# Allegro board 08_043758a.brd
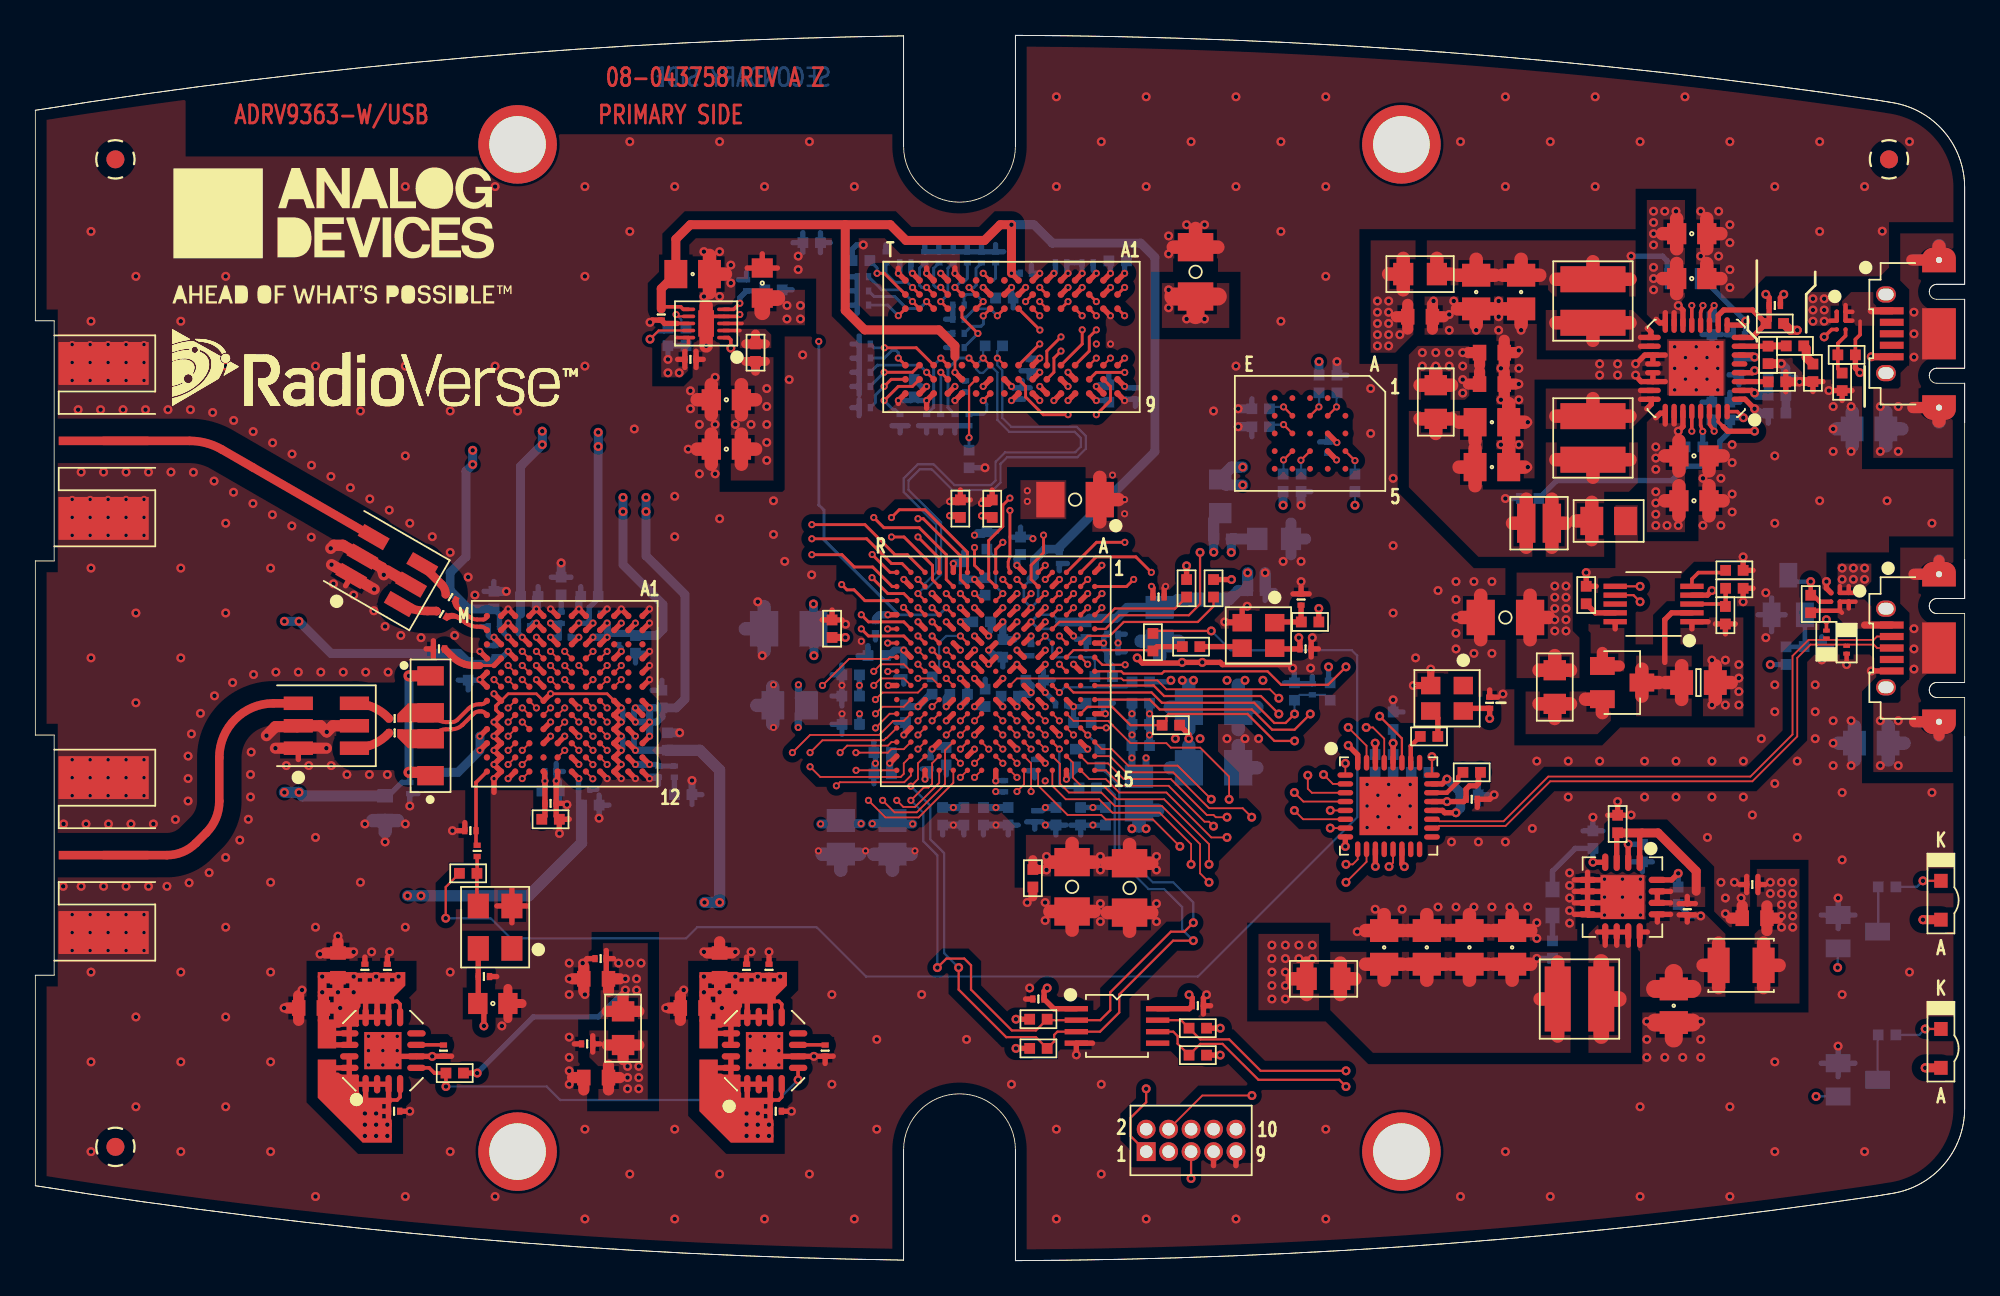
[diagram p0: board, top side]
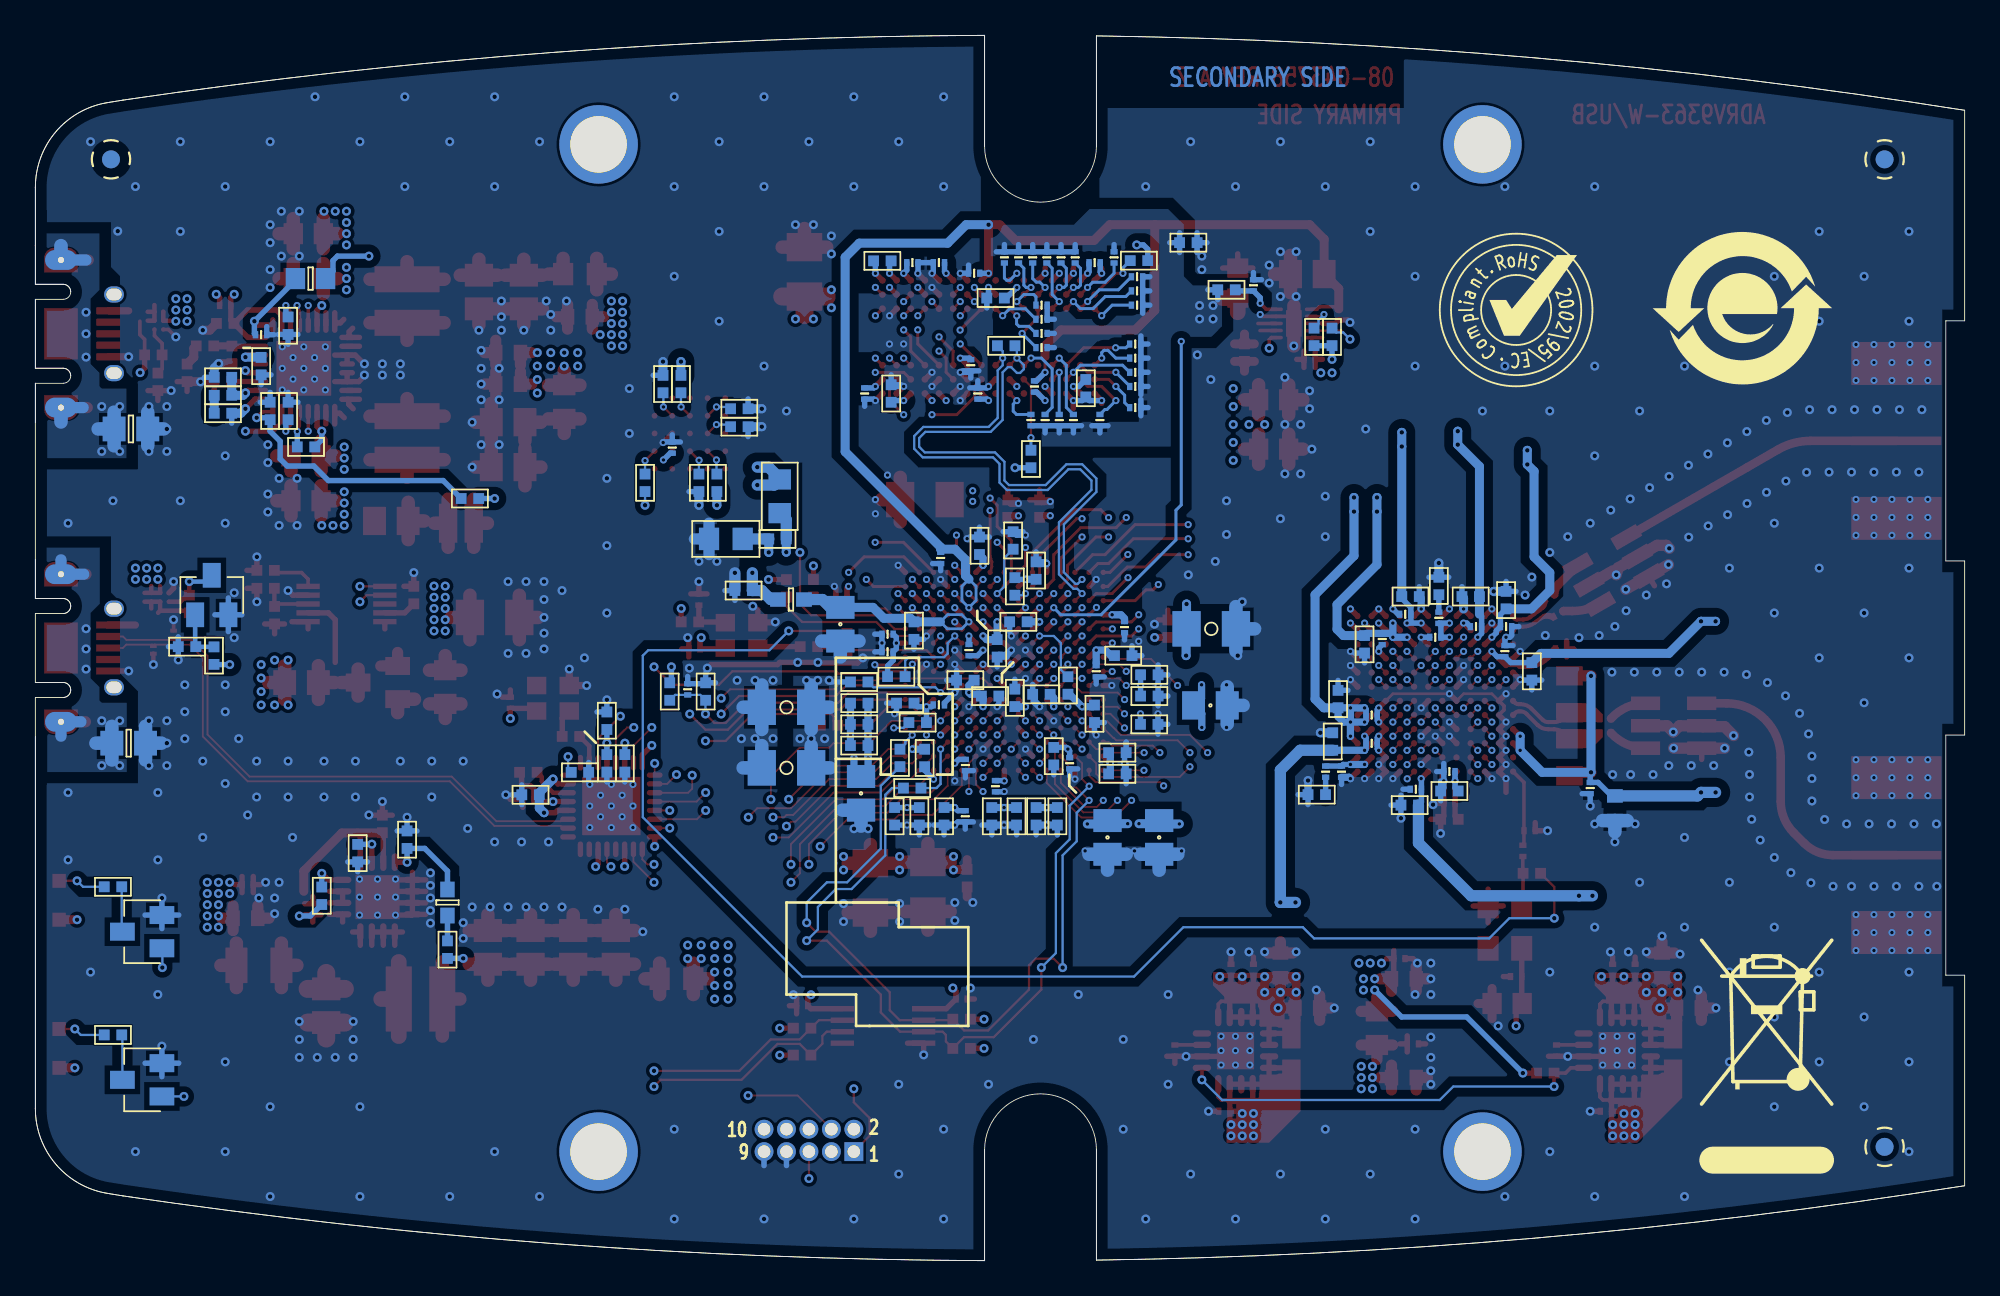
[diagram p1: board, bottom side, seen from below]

Outline 109.14 x 69.34 mm; copper layers: TOP, L2_GND, L3_PWR, L4_GND, L5_SIG, L6_SIG, L7_GND, L8_PWR, L9_GND, BOTTOM. Coordinates in mm from the lower left corner of the outline.
Outline path: 0,65.1 arc(24.48,68.08) 49.11,69.31 ; 0,65.1 arc(24.48,68.08) 49.11,69.31 ; 0,65.1 0,53.18 1.07,53.18 1.07,39.59 0,39.59 0,29.74 1.07,29.74 1.07,16.15 0,16.15 0,4.24 ; 49.11,69.31 49.11,63.06 ; 49.11,69.31 49.11,63.06 ; 0,4.24 arc(24.48,1.26) 49.11,0.03 ; 0,4.24 arc(24.48,1.26) 49.11,0.03 ; 49.11,63.06 arc(52.28,59.9) 55.44,63.06 ; 49.11,6.28 49.11,0.03 ; 49.11,6.28 arc(52.28,9.44) 55.44,6.28 ; 49.11,6.28 49.11,0.03 ; 55.44,6.28 55.44,0 ; 55.44,6.28 55.44,0 ; 55.44,69.34 55.44,63.06 ; 55.44,69.34 arc(79.87,68.37) 104.18,65.67 ; 55.44,69.34 arc(79.87,68.37) 104.18,65.67 ; 55.44,69.34 55.44,63.06 ; 104.18,65.67 105.05,65.53 ; 104.18,65.67 105.05,65.53 ; 55.44,0 arc(79.87,0.97) 104.18,3.67 ; 55.44,0 arc(79.87,0.97) 104.18,3.67 ; 105.05,65.53 arc(107.98,63.88) 109.14,60.73 ; 105.05,65.53 arc(107.98,63.88) 109.14,60.73 ; 104.18,3.67 105.05,3.81 ; 104.18,3.67 105.05,3.81 ; 105.05,3.81 arc(107.98,5.45) 109.14,8.61 ; 105.05,3.81 arc(107.98,5.45) 109.14,8.61 ; 109.14,60.73 109.14,57.47 ; 109.14,60.73 109.14,57.47 ; 107.14,54.82 arc(107.26,55.12) 107.56,55.25 ; 107.14,54.82 arc(107.26,55.12) 107.56,55.25 ; 107.14,54.82 arc(107.26,54.52) 107.56,54.4 109.14,54.4 ; 107.56,55.25 109.14,55.25 ; 107.56,55.25 109.14,55.25 ; 107.14,50.07 arc(107.26,50.37) 107.56,50.5 ; 107.14,50.07 arc(107.26,50.37) 107.56,50.5 ; 107.14,50.07 arc(107.26,49.77) 107.56,49.65 109.14,49.65 ; 107.56,50.5 109.14,50.5 ; 107.56,50.5 109.14,50.5 ; 107.14,37.04 arc(107.26,37.34) 107.56,37.47 ; 107.14,37.04 arc(107.26,37.34) 107.56,37.47 ; 107.14,37.04 arc(107.26,36.74) 107.56,36.62 ; 107.14,37.04 arc(107.26,36.74) 107.56,36.62 ; 107.56,37.47 109.14,37.47 ; 107.56,37.47 109.14,37.47 ; 107.14,32.29 arc(107.26,32.59) 107.56,32.72 ; 107.14,32.29 arc(107.26,32.59) 107.56,32.72 ; 107.14,32.29 arc(107.26,31.99) 107.56,31.87 ; 107.14,32.29 arc(107.26,31.99) 107.56,31.87 ; 107.56,32.72 109.14,32.72 ; 107.56,32.72 109.14,32.72 ; 109.14,55.25 109.14,57.47 ; 109.14,55.25 109.14,57.47 ; 109.14,54.4 109.14,50.5 ; 109.14,54.4 109.14,50.5 ; 109.14,49.65 109.14,47.43 ; 109.14,49.65 109.14,47.43 ; 109.14,37.47 109.14,39.69 ; 109.14,37.47 109.14,39.69 ; 107.56,36.62 109.14,36.62 109.14,32.72 ; 107.56,31.87 109.14,31.87 109.14,29.65 ; 109.14,47.43 109.14,39.69 ; 109.14,29.65 109.14,8.61 ; 109.14,29.65 109.14,8.61

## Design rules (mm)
net group DDR3_CK: nets DDR3_CK_N DDR3_CK_P
net group DDR3_DQS0: nets DDR3_DQS0_N DDR3_DQS0_P
net group DDR3_DQS1: nets DDR3_DQS1_N DDR3_DQS1_P
net group RX1A: nets RX1A_N RX1A_P
net group TX1A: nets TX1A_N TX1A_P
net group UART: nets UART_RX UART_TX
net group USB_OTG: nets USB_OTG_N USB_OTG_P
net group CTRL_IN: nets CTRL_IN0 CTRL_IN1 CTRL_IN2 CTRL_IN3
net group CTRL_OUT: nets IO_L08_34_CTRL_OUT0 IO_L08_34_CTRL_OUT1 IO_L13_34_CTRL_OUT2 IO_L13_34_CTRL_OUT3 IO_L21_34_CTRL_OUT4 IO_L21_34_CTRL_OUT5 IO_L22_34_CTRL_OUT6 IO_L22_34_CTRL_OUT7
net group JTAG: nets JTAG_TCK JTAG_TDI JTAG_TDO JTAG_TMS
net group PWR: nets VCCPLL VDD33_USB VDDA1P1_RX_VCO VTTVREF
net group QSPI: nets PS_MIO01_500_QSPI0_SS_B PS_MIO02_500_QSPI0_IO0 PS_MIO03_500_QSPI0_IO1 PS_MIO04_500_QSPI0_IO2 PS_MIO05_500_QSPI0_IO3 PS_MIO06_500_QSPI0_SCLK
net group RF: nets UNNAMED_7_CAP_I39_N2 UNNAMED_7_CAP_I40_N2 UNNAMED_7_CAP_I51_N1 UNNAMED_7_CAP_I52_N1 UNNAMED_7_CNBNC5P_I55_CNTR UNNAMED_7_CNBNC5P_I56_CNTR
net group RX: nets IO_L01_34_RX_D0 IO_L01_34_RX_D1 IO_L02_34_RX_D2 IO_L02_34_RX_D3 IO_L03_34_RX_D4 IO_L03_34_RX_D5 IO_L04_34_RX_D6 IO_L04_34_RX_D7 IO_L05_34_RX_D8 IO_L05_34_RX_D9 IO_L06_34_RX_D10 IO_L06_34_RX_D11 IO_L07_34_RX_FRAME IO_L12_MRCC_34_DATA_CLK
net group SPI: nets IO_L23_35_SPI_CLK IO_L23_35_SPI_ENB IO_L24_35_SPI_DI IO_L24_35_SPI_DO
net group TX: nets IO_L01_34_FB_CLK IO_L09_34_TX_FRAME IO_L15_34_TX_D0 IO_L15_34_TX_D1 IO_L16_34_TX_D2 IO_L16_34_TX_D3 IO_L17_34_TX_D4 IO_L17_34_TX_D5 IO_L18_34_TX_D6 IO_L18_34_TX_D7 IO_L19_34_TX_D8 IO_L19_34_TX_D9 IO_L20_34_TX_D10 IO_L20_34_TX_D11
net group USB_ULPI: nets PS_MIO28_501_USB0_D4 PS_MIO29_501_USB0_DIR PS_MIO30_501_USB0_STP PS_MIO31_501_USB0_NXT PS_MIO32_501_USB0_D0 PS_MIO33_501_USB0_D1 PS_MIO34_501_USB0_D2 PS_MIO35_501_USB0_D3 PS_MIO36_501_USB0_CLK PS_MIO37_501_USB0_D5 PS_MIO38_501_USB0_D6 PS_MIO39_501_USB0_D7

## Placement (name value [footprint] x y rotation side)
C1  0.1uF  [C0201]  20.29 8.46 0 top
C2  0.01UF  [C0201]  23.09 11.88 270 top
C3  10UF  [C0603#2]  15.59 14.3 180 top
C4  10UF  [C0603#2]  17.12 16.71 90 top
C5  0.1uF  [C0201]  18.64 16.46 90 top
C6  0.1uF  [C0201]  19.91 16.46 90 top
C7  0.047UF  [C0402]  94.84 48.08 270 bottom
C8  0.1uF  [C0201]  97.13 21.28 180 top
C9  10UF  [C0603#2]  97.25 19.38 180 top
C10  0.1uF  [C0201]  41.88 8.46 0 top
C11  47uF  [C0805H60]  92.68 14.42 270 top
C12  0.01UF  [C0201]  44.68 11.88 270 top
C13  0.1uF  [C0201#2]  89.51 24.71 90 top
C14  10UF  [C0603#2]  38.71 16.71 90 top
C15  10UF  [C0603#2]  37.18 14.3 180 top
C16  0.1uF  [C0201]  40.23 16.46 90 top
C17  47uF  [C0805H60]  81.13 17.73 90 top
C18  0.1uF  [C0201]  41.5 16.46 90 top
C19  47uF  [C0805H60]  76.3 17.73 90 top
C20  47uF  [C0805H60]  78.71 17.73 90 top
C21  47uF  [C0805H60]  83.54 17.73 90 top
C22  10UF  [C0603#2]  31.72 10.36 180 top
C23  0.01UF  [C0201]  31.65 36.58 0 bottom
C24  0.01UF  [C0201]  25.94 35.88 180 bottom
C25  0.1uF  [C0201]  31.21 12.27 180 top
C26  0.01UF  [C0201]  31.05 26.68 0 bottom
C27  0.01UF  [C0201]  33.54 30.88 180 bottom
C28  1uF  [C0402]  31.35 37.58 180 bottom
C29  1uF  [C0402]  25.94 37.38 90 bottom
C30  1uF  [C0402]  31.39 25.78 0 bottom
C31  1uF  [C0402]  35.45 31.78 90 bottom
C32  10UF  [C0603#2]  31.72 15.95 180 top
C33  0.1uF  [C0201]  31.98 17.09 180 top
C34  1uF  [C0402]  27.94 37.58 0 bottom
C35  1uF  [C0402]  35.75 29.38 90 bottom
C36  1uF  [C0402]  24.48 33.35 270 bottom
C37  1uF  [C0402]  33.95 34.88 270 bottom
C38  1uF  [C0402]  29.15 26.58 0 bottom
C39  0.01UF  [C0201]  27.64 35.88 0 bottom
C40  0.01UF  [C0201]  33.54 29.28 180 bottom
C41  0.01UF  [C0201]  26.01 34.49 90 bottom
C42  0.01UF  [C0201]  32.95 35.18 270 bottom
C43  0.01UF  [C0201]  29.14 25.88 0 top
C44  0.01UF  [C0201]  29.15 27.68 0 bottom
C45  1uF  [C0402]  29.14 24.98 0 top
C46  0.1uF  [C0201]  71.85 34.62 0 top
C47  0.1uF  [C0201]  72.24 32.33 90 bottom
C48  0.1uF  [C0201]  73.11 46.01 90 bottom
C49  100uF  [C1206H71]  66.65 31.32 0 bottom
C50  4.7uF  [C0402]  62.53 31.55 0 bottom
C51  0.47uF  [C0402]  47.6 34.24 180 bottom
C52  0.1uF  [C0201]  60.93 35.45 0 bottom
C53  0.01UF  [C0201]  60.93 34.45 0 bottom
C54  100uF  [C1206H71]  58.82 43.06 0 top
C55  4.7uF  [C0402]  55.73 40.45 90 bottom
C56  0.47uF  [C0402]  45.07 35.76 90 top
C57  0.47uF  [C0402]  54.13 42.55 90 top
C58  0.47uF  [C0402]  52.33 42.55 90 top
C59  0.47uF  [C0402]  52.53 39.05 90 bottom
C60  0.1uF  [C0201]  63.54 37.56 0 top
C61  0.01UF  [C0201]  47.52 35.85 270 bottom
C62  0.01UF  [C0201]  37.06 51 180 top
C63  0.01UF  [C0201]  56.03 55.88 180 bottom
C64  100uF  [C1206H71]  61.9 21.09 270 top
C65  47uF  [C0805H60]  48.49 23.95 270 bottom
C66  4.7uF  [C0402]  53.73 31.85 90 bottom
C67  4.7uF  [C0402]  52.53 25.14 270 bottom
C68  0.47uF  [C0402]  56.43 21.64 270 top
C69  0.47uF  [C0402]  59.93 31.55 0 bottom
C70  0.47uF  [C0402]  54.73 34.65 270 bottom
C71  100uF  [C1206H71]  58.65 21.16 270 top
C72  0.47uF  [C0402]  52.23 32.05 0 bottom
C73  4.7uF  [C0402]  53.53 36.15 0 bottom
C74  0.47uF  [C0402]  55.13 31.95 180 bottom
C75  0.47uF  [C0402]  56.53 32.85 0 bottom
C76  100uF  [C1206H71]  42.62 35.75 180 bottom
C77  47uF  [C0805H60]  42.67 31.42 180 bottom
C78  4.7uF  [C0402]  46.12 31.95 180 bottom
C79  10UF  [C0603]  41.12 55.32 90 top
C80  0.01UF  [C0201]  40.23 55.19 90 bottom
C81  0.22UF  [C0805]  37.18 55.83 0 top
C82  10UF  [C0603]  39.09 45.92 180 top
C83  10UF  [C0603]  39.09 48.71 180 top
C84  0.01UF  [C0201]  35.41 53.54 270 top
C85  47uF  [C0805H60]  63.6 36.01 270 bottom
C86  4.7uF  [C0402]  49.72 49.37 270 bottom
C87  4.7uF  [C0402]  60.73 49.07 90 bottom
C88  0.47uF  [C0402]  61.23 56.58 180 bottom
C89  0.47uF  [C0402]  54.82 54.47 0 bottom
C90  0.47uF  [C0402]  46.12 33.15 180 bottom
C91  0.1uF  [C0201]  55.82 49.07 90 bottom
C92  0.1uF  [C0201]  56.22 50.67 270 bottom
C93  0.47uF  [C0402]  67.16 40.84 0 bottom
C94  0.1uF  [C0201]  59.52 56.48 180 bottom
C95  0.1uF  [C0201]  58.02 56.48 0 bottom
C96  0.1uF  [C0201]  49.22 56.47 180 bottom
C97  0.1uF  [C0201]  62.23 49.07 270 bottom
C98  0.1uF  [C0201]  56.33 34.55 90 bottom
C99  0.01UF  [C0201]  57.92 39.76 90 bottom
C100  100uF  [C1206H71]  65.63 55.95 90 top
C101  4.7uF  [C0402]  43.91 57.6 180 bottom
C102  0.01UF  [C0201]  52.62 49.47 270 bottom
C103  47uF  [C0805H60]  62.43 26.44 270 bottom
C104  47uF  [C0805H60]  45.57 23.95 270 bottom
C105  4.7uF  [C0402]  55.03 25.14 270 bottom
C106  4.7uF  [C0402]  51.33 25.14 270 bottom
C107  4.7uF  [C0402]  60.53 25.14 270 bottom
C108  4.7uF  [C0402]  46.13 30.35 180 bottom
C109  0.47uF  [C0402]  53.63 25.14 270 bottom
C110  0.47uF  [C0402]  51.53 28.55 270 bottom
C111  0.47uF  [C0402]  58.83 28.44 270 bottom
C112  0.47uF  [C0402]  47.93 28.75 180 bottom
C113  0.47uF  [C0402]  59.13 25.14 270 bottom
C114  0.47uF  [C0402]  47.93 27.55 180 bottom
C115  0.47uF  [C0402]  57.74 25.14 270 bottom
C116  0.47uF  [C0402]  49.22 30.95 270 bottom
C117  0.1uF  [C0201]  56.53 25.14 270 bottom
C118  0.1uF  [C0201]  50.63 28.15 270 bottom
C119  0.01UF  [C0201]  54.83 26.85 270 bottom
C120  0.01UF  [C0201]  49.13 33.35 270 bottom
C121  10UF  [C0603]  25.88 14.55 0 top
C122  0.1uF  [C0201]  25.37 16.08 0 top
C123  18pF  [C0201]  24.99 23.19 90 top
C124  18pF  [C0201]  24.61 24.33 180 top
C125  1000pF  [C0201]  29.94 35.28 180 bottom
C126  1uF  [C0402]  29.74 38.18 270 bottom
C127  1uF  [C0402]  36.65 26.37 0 bottom
C128  1000pF  [C0201]  35.25 27.67 270 bottom
C129  1000pF  [C0201]  21.18 26.74 90 bottom
C130  10UF  [C0603#2]  19.78 25.6 270 bottom
C131  18pF  [C0201]  20.32 29.86 180 top
C132  18pF  [C0201]  20.32 30.67 180 top
C133  18pF  [C0201]  22.98 36.59 330 top
C134  18pF  [C0201]  23.49 37.55 330 top
C135  10UF  [C0603]  93.83 45.54 0 top
C136  10UF  [C0603]  93.7 55.57 0 top
C137  10UF  [C0603]  93.83 43 0 top
C138  10UF  [C0603]  93.7 58.11 0 top
C139  0.047UF  [C0402]  94.84 52.91 90 bottom
C140  1uF  [C0402]  76.81 30.55 90 bottom
C141  1uF  [C0402]  98.4 53.03 0 top
C142  150pF  [C0402]  98.52 49.98 180 bottom
C143  180pF  [C0402]  98.02 51.25 90 top
C144  3300pF  [C0402]  99.54 51.76 0 top
C145  47uF  [C0805H60]  81.51 54.81 270 top
C146  22UF  [C0805H53]  89 41.86 0 top
C147  5600pF  [C0402]  98.52 47.95 0 bottom
C148  47uF  [C0805H60]  84.05 54.81 270 top
C149  47uF  [C0805H60]  82.4 47.44 0 top
C150  47uF  [C0805H60]  82.4 44.9 0 top
C151  10UF  [C0603#2]  78.33 53.41 0 top
C152  10UF  [C0603#2]  82.4 51.38 0 top
C153  10UF  [C0603#2]  82.4 49.6 0 top
C154  1uF  [C0402]  75.79 28.14 270 bottom
C155  0.047UF  [C0402]  87.73 37.67 90 top
C156  0.47uF  [C0402]  96.11 39.06 0 top
C157  100uF  [C1206H71]  83.16 36.4 180 top
C158  100uF  [C1206H71]  66.65 27.89 0 bottom
C159  4.7uF  [C0402]  62.53 30.35 0 bottom
C160  0.47uF  [C0402]  62.53 29.15 0 bottom
C161  0.1uF  [C0201]  56.53 28.05 270 bottom
C162  0.01UF  [C0201]  58.03 31.45 180 bottom
C163  0.1uF  [C0201]  82.27 31.57 270 top
C164  0.1uF  [C0201]  81.25 26.11 0 top
C165  2.2uF  [C0402]  81.13 26.36 0 bottom
C166  0.1uF  [C0201]  56.74 14.81 0 top
C167  0.1uF  [C0201]  65.76 14.42 0 top
C168  1uF  [C0402]  76.81 28.14 270 bottom
C174  4.7uF  [C0402]  69.07 37.92 0 bottom
C178  0.47uF  [C0402]  59.44 35.65 270 bottom
D1  SESD0201X1UN-0020-09  [D0201]  102.46 34.57 270 top
D2  SESD0201X1UN-0020-09  [D0201]  101.32 35.43 90 top
DS1  LTST-S220TBKT  [LED0804]  107.8 20.39 270 top
DS2  LTST-S220TBKT  [LED0804]  107.8 12.01 270 top
E1  100OHM  [L0805]  72.87 15.95 180 top
E2  100OHM  [L0805]  78.33 55.83 180 top
E3  100OHM  [L0805]  79.22 48.59 90 top
E4  100OHM  [L0805]  33.25 13.15 90 top
E5  100OHM  [L0805]  67.03 43.25 270 bottom
E6  100OHM  [L0805]  70.08 40.84 180 bottom
E7  100OHM  [L0805]  85.95 32.46 90 top
L1  0.47uH  [L1210H67]  96.49 16.71 180 top
L2  1.5uH  [LSMSQ157H83]  88.11 54.3 90 top
L3  1.5uH  [LSMSQ157H83]  88.11 46.56 270 top
L4  1uH  [LSMSQ157H83]  87.35 14.81 180 top
L5  180NH  [LSMSQ79H41]  85.06 41.73 180 top
L8  330nH  [L0805-F]  22.36 28.49 90 top
L9  330nH  [L0805-F]  22.36 32.05 270 top
L12  600OHMS  [L0603]  66.39 37.41 180 bottom
NOREF  -  []  108.15 5.67 0 top
NOREF#2  -  [unnamed#2]  4.53 62.32 0 top
NOREF#3  -  []  52.28 63.06 0 top
NOREF#4  -  []  69.79 0.36 0 top
NOREF#5  -  []  202.3 71.42 0 top
NOREF#6  -  []  -88.22 48.51 0 top
NOREF#7  -  []  297.27 339.09 0 top
NOREF#8  -  [unnamed#2]  77.28 63.17 180 top
NOREF#9  -  []  -98.72 -116.59 0 top
NOREF#10  -  []  109.14 36.62 0 top
NOREF#11  -  []  0 4.24 0 top
NOREF#12  -  []  109.14 50.5 0 top
NOREF#13  -  []  109.14 54.4 0 top
NOREF#14  -  []  0 29.74 0 top
NOREF#15  -  []  -98.72 -116.59 0 top
NOREF#16  -  []  27.28 6.17 0 top
NOREF#17  -  [unnamed#2]  104.86 62.32 0 top
NOREF#18  -  []  109.14 8.61 0 top
NOREF#19  -  [unnamed#2]  27.28 63.17 180 top
NOREF#20  -  []  109.46 31.95 0 top
NOREF#21  -  []  0 65.1 0 top
NOREF#22  -  [unnamed#2]  27.28 6.17 180 top
NOREF#23  -  []  51.64 6.28 0 top
NOREF#24  -  []  17.37 57.99 0 top
NOREF#25  -  []  49.11 0.03 0 top
NOREF#26  -  []  1.07 16.15 0 top
NOREF#27  -  []  -98.72 -116.59 0 top
NOREF#28  -  [unnamed#2]  4.53 6.44 0 top
NOREF#29  -  []  0 39.59 0 top
NOREF#30  -  []  -37.76 254.25 0 top
NOREF#31  -  []  55.44 0 0 top
NOREF#32  -  []  52.28 6.28 0 top
NOREF#33  -  []  -98.72 -116.59 0 top
NOREF#34  -  []  49.11 0.03 0 top
NOREF#35  -  []  0 53.18 0 top
NOREF#36  -  []  27.28 6.17 0 top
NOREF#37  -  [unnamed#2]  77.28 6.17 180 top
NOREF#38  -  []  0 4.24 0 top
NOREF#39  -  []  109.14 31.87 0 top
NOREF#40  -  []  109.14 49.65 0 top
NOREF#41  -  []  109.14 37.47 0 top
NOREF#42  -  []  109.14 55.25 0 top
NOREF#43  -  []  0 16.15 0 top
NOREF#44  -  []  49.11 69.31 0 top
NOREF#45  -  []  55.44 0 90 top
NOREF#46  -  []  109.14 32.72 0 top
NOREF#47  -  []  0 65.1 0 top
NOREF#48  -  []  12.57 53.9 180 bottom
NOREF#49  -  [unnamed#2]  104.86 62.32 180 bottom
NOREF#50  -  [unnamed#2]  4.53 6.44 180 bottom
NOREF#51  -  [unnamed#2]  4.53 62.32 180 bottom
NOREF#52  -  []  1.93 21.82 180 bottom
NOREF#53  -  []  25.37 53.79 180 bottom
P1  FTSH-105-01-L-D  [CNHDR2X5H219]  62.84 6.17 0 top
P2  47590-0001  [CNMOLEX47590-0001]  109.14 34.67 180 top
P3  47590-0001  [CNMOLEX47590-0001]  109.14 52.45 180 top
Q1  BSS138LT1G  [SOT23]  103.1 18.62 90 bottom
Q2  BSS138LT1G  [SOT23]  99.16 37.67 180 bottom
Q3  SI2304BDS-T1-E3  [SOT23]  89.76 32.71 270 top
Q4  BSS138LT1G  [SOT23]  103.1 10.23 90 bottom
R1  10  [R0201]  93.44 19.89 270 top
R2  27.4K  [R0402]  88.11 23.82 270 bottom
R3  46.4K  [R0402]  90.9 23.06 90 bottom
R4  17.8K  [R0603#2]  85.82 20.27 270 bottom
R5  10K  [R0402]  23.72 10.61 180 top
R6  10K  [R0402]  92.94 20.65 90 bottom
R7  1K  [R0402]  85.82 17.6 270 bottom
R8  10K  [R0402]  72.11 36.14 180 top
R9  10K  [R0201]  71.6 37.41 90 top
R10  0  [R0402]  63.22 35 270 top
R11  0  [R0402]  74.65 44.02 270 bottom
R12  39  [R0402]  65.38 34.74 180 top
R13  20K  [R0402]  73.25 32.2 270 bottom
R14  240  [R0402]  72.62 49.6 270 bottom
R15  0  [R0402]  71.22 32.2 90 bottom
R16  120  [R0201]  51.92 56.77 90 bottom
R17  120  [R0201]  46.82 54.88 180 bottom
R18  120  [R0201]  46.91 50.27 180 bottom
R19  120  [R0201]  48.92 47.57 270 bottom
R20  120  [R0201]  46.92 48.27 180 bottom
R21  120  [R0201]  52.02 47.57 270 bottom
R22  120  [R0201]  46.92 51.87 180 bottom
R23  120  [R0201]  51.12 56.77 90 bottom
R24  120  [R0201]  50.32 56.77 90 bottom
R25  120  [R0201]  48.12 56.77 90 bottom
R26  120  [R0201]  46.82 55.68 180 bottom
R27  120  [R0201]  46.91 49.47 180 bottom
R28  120  [R0201]  50.42 47.57 270 bottom
R29  120  [R0201]  46.92 51.07 180 bottom
R30  120  [R0201]  51.22 47.57 270 bottom
R31  120  [R0201]  52.22 54.07 180 bottom
R32  120  [R0201]  52.22 52.47 180 bottom
R33  120  [R0201]  54.32 56.77 90 bottom
R34  120  [R0201]  46.82 54.07 180 bottom
R35  120  [R0201]  52.72 56.77 90 bottom
R36  120  [R0201]  52.22 51.67 180 bottom
R37  120  [R0201]  52.22 53.27 180 bottom
R38  120  [R0201]  52.82 47.57 270 bottom
R39  120  [R0201]  53.52 56.77 90 bottom
R40  240  [R0402]  53.83 40.75 90 bottom
R41  240  [R0402]  53.73 38.15 90 bottom
R42  1K  [R0402]  46.71 56.59 180 bottom
R43  0  [R0402]  41.76 54.94 180 bottom
R44  0  [R0402]  40.74 51.38 90 top
R45  0  [R0402]  60.43 33.05 180 bottom
R46  4.7K  [R0402]  50.73 32.55 270 bottom
R47  4.7K  [R0402]  65.12 38.05 90 top
R48  470  [R0402]  104.75 21.16 180 bottom
R49  14.3K  [R0201]  22.83 34.62 0 top
R50  0  [R0402]  24.48 21.92 0 top
R51  1  [R0201]  29.74 36.38 270 bottom
R52  1  [R0201]  36.15 27.67 270 bottom
R53  27.4K  [R0402]  98.52 49.73 180 top
R54  4.7K  [R0402]  96.37 50.62 270 bottom
R55  1K  [R0805]  103.86 29.28 180 bottom
R56  10  [R0201]  98.4 54.05 180 top
R58  1K  [R0805]  103.73 47.06 180 bottom
R59  100K  [R0402]  93.83 46.05 180 bottom
R60  10K  [R0402]  98.52 48.97 0 bottom
R61  10K  [R0402]  100.56 50.24 90 top
R62  17.8K  [R0603]  93.57 55.57 0 bottom
R63  14.3K  [R0201]  96.37 52.4 180 bottom
R64  46.4K  [R0402]  84.55 43.13 180 bottom
R65  23.2K  [R0402]  95.86 48.08 270 bottom
R66  240  [R0402]  99.03 34.24 90 bottom
R67  10K  [R0402]  100.56 34.74 0 bottom
R68  10K  [R0402]  102.46 51.25 180 top
R69  10K  [R0402]  102.21 49.73 270 top
R70  10K  [R0402]  100.43 37.16 90 top
R71  10K  [R0402]  95.6 36.52 90 top
R72  10K  [R0402]  96.11 38.05 0 top
R73  0.05  [R0805]  94.08 32.71 180 top
R74  10K  [R0402]  64.23 30.3 180 top
R75  10K  [R0402]  81.25 27.63 180 top
R76  20K  [R0402]  59.23 30.45 0 bottom
R77  8.06K  [R0402]  78.33 27.63 180 bottom
R78  4.7K  [R0402]  56.74 12.01 0 top
R79  4.7K  [R0402]  56.74 13.66 0 top
R80  4.7K  [R0402]  65.76 11.63 180 top
R81  4.7K  [R0402]  65.76 13.15 180 top
R82  39  [R0402]  78.84 29.66 0 top
R83  20K  [R0402]  62.53 32.75 180 bottom
R84  20K  [R0402]  66.65 38.05 90 top
R85  0  [R0402]  59.54 26.74 0 bottom
R86  0  [R0402]  60.23 28.45 270 bottom
R87  470  [R0402]  104.75 12.77 180 bottom
R116  20K  [R0402]  73.63 49.6 90 bottom
R119  20K  [R0402]  69.31 48.21 180 bottom
R120  20K  [R0402]  69.31 47.19 180 bottom
R121  20K  [R0402]  71.6 44.02 270 bottom
R122  20K  [R0402]  70.58 44.02 270 bottom
R142  80.6  [R0402]  54.22 51.77 180 bottom
R165  240  [R0402]  52.82 45.36 270 bottom
R221  10K  [R0402]  35.79 52.27 90 bottom
R222  10K  [R0402]  36.8 52.27 90 bottom
RX1A  142-0701-871  [CNSMARAL687W375H171]  3.61 46.39 180 top
T1  TCM1-63AX+  [TSML150W160H160]  19.88 39.05 60 top
T5  TCM1-63AX+  [TSML150W160H160]  16.46 30.27 90 top
TX1A  142-0701-871  [CNSMARAL687W375H171]  3.61 22.95 180 top
U1  ADP1754ACPZ-1.3  [QFN16_4X4_PAD2_1X2_1]  19.66 11.88 0 top
U2  MT41K256M16TW-107 IT:P  [FBGA96_C]  55.22 52.27 180 top
U3  ADP2164ACPZ  [QFN16_4X4_PAD2_5X2_5]  89.78 20.57 180 top
U4  XC7Z010-1CLG225C  [CSPBGA225]  54.33 33.35 180 top
U5  AD9363ABCZ  [BGA144-2]  29.94 32.08 180 top
U6  ADP2114ACPZ  [QFN32_5X5_PAD3_1X3_1]  93.95 50.49 90 top
U7  ADP1754ACPZ-1.3  [QFN16_4X4_PAD2_1X2_1]  41.25 11.88 0 top
U8  NCP339AFCT2G  [WLCSP6]  102.15 53.19 270 top
U9  NCP339AFCT2G  [WLCSP6]  102.08 37.54 180 top
U10  ADM1177-1ARMZ  [RM10]  91.54 37.16 90 top
U11  TCA9517DGKR  [MSOP8]  61.19 13.28 270 top
U13  N25Q256A11E1240  [TBGA24]  72.11 46.81 180 top
U14  TPS51206DSQR  [SON10_2X2_PAD1_5X0_9]  37.95 53.03 90 top
U15  USB3320C-EZK  [QFN32_5X5_PAD3_3X3_3]  76.55 25.73 270 top
Y1  24.000MEGHZ  [YSML98W79H35]  79.86 31.82 180 top
Y2  33.333MEGHZ  [YSML98W79H35]  69.19 35.38 180 top
Y3  40MEGHz  [YSML126W98H47]  26.01 18.87 90 top

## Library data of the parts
C1 C5 C6 C8 C10 C16 C18 C25 C33 C46-C48 C52 C60 C91 C92 C94-C98 C117 C118 C122 C161 C163 C164 C166 C167 = CAP: User Part Number: UPN; Tolerance: 20; part number: CAP_SM-0.1UF,16V,20,E017331,C0201; tolerance: 20
C2 C12 C23 C24 C26 C27 C39-C44 C53 C61-C63 C80 C84 C99 C102 C119 C120 C162 = CAP: User Part Number: UPN; Tolerance: 10; part number: CAP_SM-0.01UF,10V,10,E007201,C0201; tolerance: 10
C3 C4 C9 C14 C15 C22 C32 C79 C82 C83 C121 C130 C135-C138 C151-C153 = CAP: Tolerance: 20; User Part Number: UPN; alternate symbols: C0603L_ALT; part number: CAP_SM-10UF,6.3V,20,E007143,C0603; tolerance: 20
C7 C139 C155 = CAP: Tolerance: 10; User Part Number: UPN; alternate symbols: C0402_ALT; part number: CAP_SM-0.047UF,25V,10,E006454,C0402; tolerance: 10
C11 C17 C19-C21 C65 C77 C85 C103 C104 C145 C148-C150 = CAP: Tolerance: 20; User Part Number: UPN; part number: CAP_SM-47UF,6.3V,20,E008247,C0805H60; tolerance: 20
C13 = CAP: Tolerance: 20; User Part Number: UPN; alternate symbols: C0402_ALT; part number: CAP_SM-0.1UF,16V,20,E017331,C0201; tolerance: 20
C28-C31 C34-C38 C45 C127 C140 C141 C154 C168 = CAP: Tolerance: 10; User Part Number: UPN; alternate symbols: C0402_ALT; part number: CAP_SM-1UF,6.3V,10,E007449,C0402; tolerance: 10
C49 C54 C64 C71 C76 C100 C157 C158 = CAP: Tolerance: 20; User Part Number: UPN; part number: CAP_SM-100UF,6.3V,20,E016591,C1206H71; tolerance: 20
C50 C55 C66 C67 C73 C78 C86 C87 C101 C105-C108 C159 C174 = CAP: Tolerance: 10; User Part Number: UPN; alternate symbols: C0402_ALT; part number: CAP_SM-4.7UF,6.3V,10,E020089,C0402; tolerance: 10
C51 C56-C59 C68-C70 C72 C74 C75 C88-C90 C93 C109-C116 C156 C160 C178 = CAP: Tolerance: 10; User Part Number: UPN; alternate symbols: C0402_ALT; part number: CAP_SM-0.47UF,10V,10,E007611,C0402; tolerance: 10
C81 = CAP: Tolerance: 10; User Part Number: UPN; part number: CAP_SM-0.22UF,16V,10,E000443,C0805; tolerance: 10
C123 C124 C131-C134 = CAP: User Part Number: UPN; Tolerance: 5; part number: CAP_SM-18PF,50V,5,E017960,C0201; tolerance: 5
C125 C128 C129 = CAP: User Part Number: UPN; Tolerance: 10; part number: CAP_SM-1000PF,25V,10,E006762,C0201; tolerance: 10
C126 = CAP: Tolerance: 10; User Part Number: UPN; alternate symbols: R0402_ALT; part number: CAP_SM-1UF,6.3V,10,E007449,C0402; tolerance: 10
C142 = CAP: Tolerance: 5; User Part Number: UPN; alternate symbols: C0402_ALT; part number: CAP_SM-150PF,50V,5,E012646,C0402; tolerance: 5
C143 = CAP: Tolerance: 5; User Part Number: UPN; alternate symbols: C0402_ALT; part number: CAP_SM-180PF,50V,5,E012612,C0402; tolerance: 5
C144 = CAP: Tolerance: 10; User Part Number: UPN; alternate symbols: C0402_ALT; part number: CAP_SM-3300PF,50V,10,E007461,C0402; tolerance: 10
C146 = CAP: Tolerance: 20; User Part Number: UPN; part number: CAP_SM-22UF,6.3V,20,E006534,C0805H53; tolerance: 20
C147 = CAP: Tolerance: 10; User Part Number: UPN; alternate symbols: C0402_ALT; part number: CAP_SM-5600PF,25V,10,E011820,C0402; tolerance: 10
C165 = CAP: Tolerance: 10; User Part Number: UPN; alternate symbols: C0402_ALT; part number: CAP_SM-2.2UF,10V,10,E017584,C0402; tolerance: 10
D1 D2 = DIO: Tolerance: N/A; User Part Number: UPN; part number: DIO_SM-SESD0201X1UN-0020-09,9V,N/A,E022225,D0201; tolerance: N/A
DS1 DS2 = DIOLED: User Part Number: UPN; Tolerance: N/A; alternate symbols: LED0804_RA; part number: DIOLED_SM-LTST-S220TBKT,3.3V,N/A,E026167,LED0804; tolerance: N/A
E1-E7 = FERRITE: Tolerance: N/A; User Part Number: UPN; part number: FERRITE_SM-100OHM,N/A,E012241,L0805; tolerance: N/A
L1 = IND: User Part Number: UPN; Tolerance: 30; part number: IND_SM-0.47UH,30,E018627,L1210H67; tolerance: 30
L2 L3 = IND: User Part Number: UPN; Tolerance: 20; part number: IND_SM-1.5UH,20,E017267,LSMSQ157H83; tolerance: 20
L4 = IND: User Part Number: UPN; Tolerance: 20; part number: IND_SM-1UH,20,E015845,LSMSQ157H83; tolerance: 20
L5 = IND: User Part Number: UPN; Tolerance: 20; part number: IND_SM-180NH,20,E026052,LSMSQ79H41; tolerance: 20
L8 L9 = IND: Tolerance: 5; User Part Number: UPN; part number: IND_SM-330NH,5,E006599,L0805-F; tolerance: 5
L12 = FERRITE: Tolerance: N/A; User Part Number: UPN; part number: FERRITE_SM-600OHMS,N/A,E007179,L0603; tolerance: N/A
P1 = CN10P_ODD_EVEN: Tolerance: N/A; User Part Number: UPN; part number: CN10P_ODD_EVEN_TH-FTSH-105-01-L-D,E018623,CNHDR2X5H219; tolerance: N/A
P2 P3 = CN5P_3SHLD: User Part Number: UPN; Tolerance: N/A; part number: CN5P_3SHLD_SM-47590-0001,E015753,CNMOLEX47590-0001; tolerance: N/A
Q1 Q2 Q4 = TRANNMOSFET_V8: User Part Number: UPN; Tolerance: N/A; part number: TRANNMOSFET_V8_SM-BSS138LT1G,E018770,SOT23; tolerance: N/A
Q3 = TRANTN0200T: User Part Number: UPN; Tolerance: N/A; part number: TRANTN0200T_SM-SI2304BDS-T1-E3,E014236,SOT23; tolerance: N/A
R1 R56 = RES: User Part Number: UPN; Tolerance: 1; part number: RES_SM-10,E013982,1/20W,1,R0201; tolerance: 1
R2 R53 = RES: Tolerance: 1; User Part Number: UPN; alternate symbols: R0402_ALT; part number: RES_SM-27.4K,E021819,1/10W,1,R0402; tolerance: 1
R3 R64 = RES: Tolerance: 1; User Part Number: UPN; alternate symbols: R0402_ALT; part number: RES_SM-46.4K,E011115,1/16W,1,R0402; tolerance: 1
R4 = RES: Tolerance: 1; User Part Number: UPN; alternate symbols: R0603_A; part number: RES_SM-17.8K,E011033,1/10W,1,R0603; tolerance: 1
R5 R6 R8 R60 R61 R67-R72 R74 R75 R221 R222 = RES: Tolerance: 1; User Part Number: UPN; alternate symbols: R0402_ALT; part number: RES_SM-10K,E003751,1/16W,1,R0402; tolerance: 1
R7 R42 = RES: Tolerance: 1; User Part Number: UPN; alternate symbols: R0402_ALT; part number: RES_SM-1K,E003763,1/10W,1,R0402; tolerance: 1
R9 = RES: User Part Number: UPN; Tolerance: 1; part number: RES_SM-10K,E004011,1/20W,1,R0201; tolerance: 1
R10 R11 R15 R43-R45 R50 R85 R86 = RES: Tolerance: 1; User Part Number: UPN; alternate symbols: R0402_ALT; part number: RES_SM-0,E010661,1/16W,1,R0402; tolerance: 1
R12 R82 = RES: Tolerance: 5; User Part Number: UPN; alternate symbols: R0402_ALT; part number: RES_SM-39,E003441,1/16W,5,R0402; tolerance: 5
R13 R76 R83 R84 R116 R119-R122 = RES: Tolerance: 1; User Part Number: UPN; alternate symbols: R0402_ALT; part number: RES_SM-20K,E003791,1/16W,1,R0402; tolerance: 1
R14 R40 R41 R66 R165 = RES: Tolerance: 1; User Part Number: UPN; alternate symbols: R0402_ALT; part number: RES_SM-240,E010877,1/16W,1,R0402; tolerance: 1
R16-R39 = RES: User Part Number: UPN; Tolerance: 1; part number: RES_SM-120,E011549,1/20W,1,R0201; tolerance: 1
R46 R47 R54 R78-R81 = RES: Tolerance: 1; User Part Number: UPN; alternate symbols: R0402_ALT; part number: RES_SM-4.7K,E008190,1/16W,1,R0402; tolerance: 1
R48 R87 = RES: Tolerance: 5; User Part Number: UPN; alternate symbols: R0402_ALT; part number: RES_SM-470,E017765,1/10W,5,R0402; tolerance: 5
R49 R63 = RES: User Part Number: UPN; Tolerance: 1; part number: RES_SM-14.3K,E014068,1/20W,1,R0201; tolerance: 1
R51 R52 = RES: User Part Number: UPN; part number: RES_SM-1,E014056,1/20W,1,R0201
R55 R58 = RES: Tolerance: 1; User Part Number: UPN; part number: RES_SM-1K,E023448,1/3W,1,R0805; tolerance: 1
R59 = RES: Tolerance: 1; User Part Number: UPN; alternate symbols: R0402_ALT; part number: RES_SM-100K,E003796,1/16W,1,R0402; tolerance: 1
R62 = RES: Tolerance: 1; User Part Number: UPN; part number: RES_SM-17.8K,E011033,1/10W,1,R0603; tolerance: 1
R65 = RES: Tolerance: 1; User Part Number: UPN; alternate symbols: R0402_ALT; part number: RES_SM-23.2K,E019517,1/16W,1,R0402; tolerance: 1
R73 = RES: Tolerance: 1; User Part Number: UPN; part number: RES_SM-0.05,E013377,1/8W,1,R0805; tolerance: 1
R77 = RES: Tolerance: 1; User Part Number: UPN; alternate symbols: R0402_ALT; part number: RES_SM-8.06K,E021385,1/10W,1,R0402; tolerance: 1
R142 = RES: Tolerance: 0.1; User Part Number: UPN; alternate symbols: R0402_ALT; part number: RES_SM-80.6,E022369,1/16W,0.1,R0402; tolerance: 0.1
RX1A TX1A = CNBNC5P: User Part Number: UPN; Tolerance: N/A; part number: CNBNC5P_SM-142-0701-871,E026289,CNSMARAL687W375H171; tolerance: N/A
T1 T5 = XFMRTCMXXXX_V3: Tolerance: N/A; User Part Number: UPN; part number: XFMRTCMXXXX_V3_SM-TCM1-63AX+,E018203,TSML150W160H160; tolerance: N/A
U1 U7 = ADP1754: Tolerance: N/A; User Part Number: UPN; part number: ADP1754_SM-ADP1754ACPZ-1.3,E022696,QFN16_4X4_PAD2_1X2_1; tolerance: N/A
U2 = ICMT41K256M16: User Part Number: UPN; Tolerance: N/A; part number: ICMT41K256M16_SM-MT41K256M16TW-107 IT:P,E025601,FBGA96_C; tolerance: N/A
U3 = ADP2164: Tolerance: N/A; User Part Number: UPN; part number: ADP2164_SM-ADP2164ACPZ,E013699,QFN16_4X4_PAD2_5X2_5; tolerance: N/A
U4 = ICXC7Z010: Tolerance: N/A; User Part Number: UPN; part number: ICXC7Z010_SM-XC7Z010-1CLG225C,E025809,CSPBGA225; tolerance: N/A
U5 = AD9363: Tolerance: N/A; User Part Number: UPN; part number: AD9363_SM-AD9363ABCZ,E026056,BGA144-2; tolerance: N/A
U6 = ADP2114: User Part Number: UPN; Tolerance: N/A; part number: ADP2114_SM-ADP2114ACPZ,E008105,QFN32_5X5_PAD3_1X3_1; tolerance: N/A
U8 U9 = ICNCP339: Tolerance: N/A; User Part Number: UPN; part number: ICNCP339_SM-NCP339AFCT2G,E025896,WLCSP6; tolerance: N/A
U10 = ADM1177: Tolerance: N/A; User Part Number: UPN; part number: ADM1177_SM-ADM1177-1ARMZ,E016506,RM10; tolerance: N/A
U11 = CMOSTCA9517: User Part Number: UPN; part number: CMOSTCA9517_SM-TCA9517DGKR,E022173,MSOP8
U13 = ICN25Q256A_V2: User Part Number: UPN; Tolerance: N/A; part number: ICN25Q256A_V2_SM-N25Q256A11E1240,E023338,TBGA24; tolerance: N/A
U14 = ICTPS51206: Tolerance: N/A; User Part Number: UPN; part number: ICTPS51206_SM-TPS51206DSQR,E021346,SON10_2X2_PAD1_5X0_9; tolerance: N/A
U15 = ICUSB3320C: Tolerance: N/A; User Part Number: UPN; part number: ICUSB3320C_SM-USB3320C-EZK,E021334,QFN32_5X5_PAD3_3X3_3; tolerance: N/A
Y1 = XTALOSC4P_V7: Tolerance: N/A; User Part Number: UPN; part number: XTALOSC4P_V7_SM-24.000MEGHZ,E022374,YSML98W79H35; tolerance: N/A
Y2 = XTALOSC4P_V7: Tolerance: N/A; User Part Number: UPN; part number: XTALOSC4P_V7_SM-33.333MEGHZ,E024048,YSML98W79H35; tolerance: N/A
Y3 = XTALOSC4P_V21: Tolerance: N/A; User Part Number: UPN; part number: XTALOSC4P_V21_SM-40MEGHZ,E020493,YSML126W98H47; tolerance: N/A

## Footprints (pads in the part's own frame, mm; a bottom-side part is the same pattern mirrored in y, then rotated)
BGA144-2
  round 0.356 smd: A1(-4.4,-4.4) A2(-4.4,-3.6) A3(-4.4,-2.8) A4(-4.4,-2) A5(-4.4,-1.2) A6(-4.4,-0.4) A7(-4.4,0.4) A8(-4.4,1.2) A9(-4.4,2) A10(-4.4,2.8) A11(-4.4,3.6) A12(-4.4,4.4) B1(-3.6,-4.4) B2(-3.6,-3.6) B3(-3.6,-2.8) B4(-3.6,-2) B5(-3.6,-1.2) B6(-3.6,-0.4) B7(-3.6,0.4) B8(-3.6,1.2) B9(-3.6,2) B10(-3.6,2.8) B11(-3.6,3.6) B12(-3.6,4.4) C1(-2.8,-4.4) C2(-2.8,-3.6) C3(-2.8,-2.8) C4(-2.8,-2) C5(-2.8,-1.2) C6(-2.8,-0.4) C7(-2.8,0.4) C8(-2.8,1.2) C9(-2.8,2) C10(-2.8,2.8) C11(-2.8,3.6) C12(-2.8,4.4) D1(-2,-4.4) D2(-2,-3.6) D3(-2,-2.8) D4(-2,-2) D5(-2,-1.2) D6(-2,-0.4) D7(-2,0.4) D8(-2,1.2) D9(-2,2) D10(-2,2.8) D11(-2,3.6) D12(-2,4.4) E1(-1.2,-4.4) E2(-1.2,-3.6) E3(-1.2,-2.8) E4(-1.2,-2) E5(-1.2,-1.2) E6(-1.2,-0.4) E7(-1.2,0.4) E8(-1.2,1.2) E9(-1.2,2) E10(-1.2,2.8) E11(-1.2,3.6) E12(-1.2,4.4) F1(-0.4,-4.4) F2(-0.4,-3.6) F3(-0.4,-2.8) F4(-0.4,-2) F5(-0.4,-1.2) F6(-0.4,-0.4) F7(-0.4,0.4) F8(-0.4,1.2) F9(-0.4,2) F10(-0.4,2.8) F11(-0.4,3.6) F12(-0.4,4.4) G1(0.4,-4.4) G2(0.4,-3.6) G3(0.4,-2.8) G4(0.4,-2) G5(0.4,-1.2) G6(0.4,-0.4) G7(0.4,0.4) G8(0.4,1.2) G9(0.4,2) G10(0.4,2.8) G11(0.4,3.6) G12(0.4,4.4) H1(1.2,-4.4) H2(1.2,-3.6) H3(1.2,-2.8) H4(1.2,-2) H5(1.2,-1.2) H6(1.2,-0.4) H7(1.2,0.4) H8(1.2,1.2) H9(1.2,2) H10(1.2,2.8) H11(1.2,3.6) H12(1.2,4.4) J1(2,-4.4) J2(2,-3.6) J3(2,-2.8) J4(2,-2) J5(2,-1.2) J6(2,-0.4) J7(2,0.4) J8(2,1.2) J9(2,2) J10(2,2.8) J11(2,3.6) J12(2,4.4) K1(2.8,-4.4) K2(2.8,-3.6) K3(2.8,-2.8) K4(2.8,-2) K5(2.8,-1.2) K6(2.8,-0.4) K7(2.8,0.4) K8(2.8,1.2) K9(2.8,2) K10(2.8,2.8) K11(2.8,3.6) K12(2.8,4.4) L1(3.6,-4.4) L2(3.6,-3.6) L3(3.6,-2.8) L4(3.6,-2) L5(3.6,-1.2) L6(3.6,-0.4) L7(3.6,0.4) L8(3.6,1.2) L9(3.6,2) L10(3.6,2.8) L11(3.6,3.6) L12(3.6,4.4) M1(4.4,-4.4) M2(4.4,-3.6) M3(4.4,-2.8) M4(4.4,-2) M5(4.4,-1.2) M6(4.4,-0.4) M7(4.4,0.4) M8(4.4,1.2) M9(4.4,2) M10(4.4,2.8) M11(4.4,3.6) M12(4.4,4.4)
C0201
  rect 0.305x0.406 smd: 1(-0.318,0) 2(0.318,0)
C0201#2
  rect 0.61x0.61 smd: 1(-0.495,0) 2(0.495,0)
C0402
  rect 0.61x0.61 smd: 1(-0.495,0) 2(0.495,0)
C0603
  rect 1.092x1.194 smd: 1(-0.851,0) 2(0.851,0)
C0603#2
  rect 0.762x0.889 smd: 1(-0.699,0) 2(0.699,0)
C0805
  rect 1.295x1.6 smd: 1(-0.953,0) 2(0.953,0)
C0805H53
  rect 1.295x1.6 smd: 1(-0.953,0) 2(0.953,0)
C0805H60
  rect 1.295x1.6 smd: 1(-0.953,0) 2(0.953,0)
C1206H71
  rect 1.6x2.007 smd: 1(-1.397,0) 2(1.397,0)
CNHDR2X5H219
  rect 1.067x1.067 hole 0.711: 1(0,0)
  round 1.067 hole 0.711: 2(0,1.27) 3(1.27,0) 4(1.27,1.27) 5(2.54,0) 6(2.54,1.27) 7(3.81,0) 8(3.81,1.27) 9(5.08,0) 10(5.08,1.27)
CNMOLEX47590-0001
  oval 1.118x0.914 hole 0.864x0.66: (4.45,2.225) (4.45,-2.225)
  rect 1.346x0.406 smd: 1(4.123,-1.3) 2(4.123,-0.65) 3(4.123,0) 4(4.123,0.65) 5(4.123,1.3)
  custom 0.349x0.349 hole 1.295x0.61: SH1(1.45,4.175) SH3(1.45,-4.175)
  rect 1.905x2.896 smd: SH2(1.45,0)
CNSMARAL687W375H171
  rect 5.08x0.483 smd: 1(-0.254,0)
  rect 5.08x2.413 smd: 2(-0.254,4.381) 3(-0.254,4.381) 4(-0.254,-4.381) 5(-0.254,-4.381)
CSPBGA225
  round 0.305 smd: A1(-5.6,-5.6) A2(-5.6,-4.8) A3(-5.6,-4) A4(-5.6,-3.2) A5(-5.6,-2.4) A6(-5.6,-1.6) A7(-5.6,-0.8) A8(-5.6,0) A9(-5.6,0.8) A10(-5.6,1.6) A11(-5.6,2.4) A12(-5.6,3.2) A13(-5.6,4) A14(-5.6,4.8) A15(-5.6,5.6) B1(-4.8,-5.6) B2(-4.8,-4.8) B3(-4.8,-4) B4(-4.8,-3.2) B5(-4.8,-2.4) B6(-4.8,-1.6) B7(-4.8,-0.8) B8(-4.8,0) B9(-4.8,0.8) B10(-4.8,1.6) B11(-4.8,2.4) B12(-4.8,3.2) B13(-4.8,4) B14(-4.8,4.8) B15(-4.8,5.6) C1(-4,-5.6) C2(-4,-4.8) C3(-4,-4) C4(-4,-3.2) C5(-4,-2.4) C6(-4,-1.6) C7(-4,-0.8) C8(-4,0) C9(-4,0.8) C10(-4,1.6) C11(-4,2.4) C12(-4,3.2) C13(-4,4) C14(-4,4.8) C15(-4,5.6) D1(-3.2,-5.6) D2(-3.2,-4.8) D3(-3.2,-4) D4(-3.2,-3.2) D5(-3.2,-2.4) D6(-3.2,-1.6) D7(-3.2,-0.8) D8(-3.2,0) D9(-3.2,0.8) D10(-3.2,1.6) D11(-3.2,2.4) D12(-3.2,3.2) D13(-3.2,4) D14(-3.2,4.8) D15(-3.2,5.6) E1(-2.4,-5.6) E2(-2.4,-4.8) E3(-2.4,-4) E4(-2.4,-3.2) E5(-2.4,-2.4) E6(-2.4,-1.6) E7(-2.4,-0.8) E8(-2.4,0) E9(-2.4,0.8) E10(-2.4,1.6) E11(-2.4,2.4) E12(-2.4,3.2) E13(-2.4,4) E14(-2.4,4.8) E15(-2.4,5.6) F1(-1.6,-5.6) F2(-1.6,-4.8) F3(-1.6,-4) F4(-1.6,-3.2) F5(-1.6,-2.4) F6(-1.6,-1.6) F7(-1.6,-0.8) F8(-1.6,0) F9(-1.6,0.8) F10(-1.6,1.6) F11(-1.6,2.4) F12(-1.6,3.2) F13(-1.6,4) F14(-1.6,4.8) F15(-1.6,5.6) G1(-0.8,-5.6) G2(-0.8,-4.8) G3(-0.8,-4) G4(-0.8,-3.2) G5(-0.8,-2.4) G6(-0.8,-1.6) G7(-0.8,-0.8) G8(-0.8,0) G9(-0.8,0.8) G10(-0.8,1.6) G11(-0.8,2.4) G12(-0.8,3.2) G13(-0.8,4) G14(-0.8,4.8) G15(-0.8,5.6) H1(0,-5.6) H2(0,-4.8) H3(0,-4) H4(0,-3.2) H5(0,-2.4) H6(0,-1.6) H7(0,-0.8) H8(0,0) H9(0,0.8) H10(0,1.6) H11(0,2.4) H12(0,3.2) H13(0,4) H14(0,4.8) H15(0,5.6) J1(0.8,-5.6) J2(0.8,-4.8) J3(0.8,-4) J4(0.8,-3.2) J5(0.8,-2.4) J6(0.8,-1.6) J7(0.8,-0.8) J8(0.8,0) J9(0.8,0.8) J10(0.8,1.6) J11(0.8,2.4) J12(0.8,3.2) J13(0.8,4) J14(0.8,4.8) J15(0.8,5.6) K1(1.6,-5.6) K2(1.6,-4.8) K3(1.6,-4) K4(1.6,-3.2) K5(1.6,-2.4) K6(1.6,-1.6) K7(1.6,-0.8) K8(1.6,0) K9(1.6,0.8) K10(1.6,1.6) K11(1.6,2.4) K12(1.6,3.2) K13(1.6,4) K14(1.6,4.8) K15(1.6,5.6) L1(2.4,-5.6) L2(2.4,-4.8) L3(2.4,-4) L4(2.4,-3.2) L5(2.4,-2.4) L6(2.4,-1.6) L7(2.4,-0.8) L8(2.4,0) L9(2.4,0.8) L10(2.4,1.6) L11(2.4,2.4) L12(2.4,3.2) L13(2.4,4) L14(2.4,4.8) L15(2.4,5.6) M1(3.2,-5.6) M2(3.2,-4.8) M3(3.2,-4) M4(3.2,-3.2) M5(3.2,-2.4) M6(3.2,-1.6) M7(3.2,-0.8) M8(3.2,0) M9(3.2,0.8) M10(3.2,1.6) M11(3.2,2.4) M12(3.2,3.2) M13(3.2,4) M14(3.2,4.8) M15(3.2,5.6) N1(4,-5.6) N2(4,-4.8) N3(4,-4) N4(4,-3.2) N5(4,-2.4) N6(4,-1.6) N7(4,-0.8) N8(4,0) N9(4,0.8) N10(4,1.6) N11(4,2.4) N12(4,3.2) N13(4,4) N14(4,4.8) N15(4,5.6) P1(4.8,-5.6) P2(4.8,-4.8) P3(4.8,-4) P4(4.8,-3.2) P5(4.8,-2.4) P6(4.8,-1.6) P7(4.8,-0.8) P8(4.8,0) P9(4.8,0.8) P10(4.8,1.6) P11(4.8,2.4) P12(4.8,3.2) P13(4.8,4) P14(4.8,4.8) P15(4.8,5.6) R1(5.6,-5.6) R2(5.6,-4.8) R3(5.6,-4) R4(5.6,-3.2) R5(5.6,-2.4) R6(5.6,-1.6) R7(5.6,-0.8) R8(5.6,0) R9(5.6,0.8) R10(5.6,1.6) R11(5.6,2.4) R12(5.6,3.2) R13(5.6,4) R14(5.6,4.8) R15(5.6,5.6)
D0201
  rect 0.229x0.381 smd: A(0.22,0) C(-0.22,0)
FBGA96_C
  round 0.381 smd: A1(-6,-3.2) A2(-6,-2.4) A3(-6,-1.6) A7(-6,1.6) A8(-6,2.4) A9(-6,3.2) B1(-5.2,-3.2) B2(-5.2,-2.4) B3(-5.2,-1.6) B7(-5.2,1.6) B8(-5.2,2.4) B9(-5.2,3.2) C1(-4.4,-3.2) C2(-4.4,-2.4) C3(-4.4,-1.6) C7(-4.4,1.6) C8(-4.4,2.4) C9(-4.4,3.2) D1(-3.6,-3.2) D2(-3.6,-2.4) D3(-3.6,-1.6) D7(-3.6,1.6) D8(-3.6,2.4) D9(-3.6,3.2) E1(-2.8,-3.2) E2(-2.8,-2.4) E3(-2.8,-1.6) E7(-2.8,1.6) E8(-2.8,2.4) E9(-2.8,3.2) F1(-2,-3.2) F2(-2,-2.4) F3(-2,-1.6) F7(-2,1.6) F8(-2,2.4) F9(-2,3.2) G1(-1.2,-3.2) G2(-1.2,-2.4) G3(-1.2,-1.6) G7(-1.2,1.6) G8(-1.2,2.4) G9(-1.2,3.2) H1(-0.4,-3.2) H2(-0.4,-2.4) H3(-0.4,-1.6) H7(-0.4,1.6) H8(-0.4,2.4) H9(-0.4,3.2) J1(0.4,-3.2) J2(0.4,-2.4) J3(0.4,-1.6) J7(0.4,1.6) J8(0.4,2.4) J9(0.4,3.2) K1(1.2,-3.2) K2(1.2,-2.4) K3(1.2,-1.6) K7(1.2,1.6) K8(1.2,2.4) K9(1.2,3.2) L1(2,-3.2) L2(2,-2.4) L3(2,-1.6) L7(2,1.6) L8(2,2.4) L9(2,3.2) M1(2.8,-3.2) M2(2.8,-2.4) M3(2.8,-1.6) M7(2.8,1.6) M8(2.8,2.4) M9(2.8,3.2) N1(3.6,-3.2) N2(3.6,-2.4) N3(3.6,-1.6) N7(3.6,1.6) N8(3.6,2.4) N9(3.6,3.2) P1(4.4,-3.2) P2(4.4,-2.4) P3(4.4,-1.6) P7(4.4,1.6) P8(4.4,2.4) P9(4.4,3.2) R1(5.2,-3.2) R2(5.2,-2.4) R3(5.2,-1.6) R7(5.2,1.6) R8(5.2,2.4) R9(5.2,3.2) T1(6,-3.2) T2(6,-2.4) T3(6,-1.6) T7(6,1.6) T8(6,2.4) T9(6,3.2)
L0603
  rect 0.889x0.813 smd: 1(-0.737,0) 2(0.737,0)
L0805
  rect 1.143x1.27 smd: 1(-0.953,0) 2(0.953,0)
L0805-F
  rect 1.092x1.499 smd: 1(-1.046,0) 2(1.046,0)
L1210H67
  rect 1.245x2.007 smd: 1(-1.272,0) 2(1.272,0)
LED0804
  rect 0.787x0.762 smd: A(1.1,0) C(-1.1,0)
LSMSQ79H41
  rect 1.041x2.21 smd: 1(-0.724,0) 2(0.724,0)
LSMSQ157H83
  rect 1.473x3.683 smd: 1(-1.232,0) 2(1.232,0)
MSOP8
  rect 0.305x1.321 smd: 1(-0.975,-2.3) 2(-0.325,-2.3) 3(0.325,-2.3) 4(0.975,-2.3) 5(0.975,2.3) 6(0.325,2.3) 7(-0.325,2.3) 8(-0.975,2.3)
QFN16_4X4_PAD2_1X2_1
  oval 0.356x1.041 smd: 1(-0.975,-1.9) 2(-0.325,-1.9) 3(0.325,-1.9) 4(0.975,-1.9) 9(0.975,1.9) 10(0.325,1.9) 11(-0.325,1.9) 12(-0.975,1.9)
  oval 1.041x0.356 smd: 5(1.9,-0.975) 6(1.9,-0.325) 7(1.9,0.325) 8(1.9,0.975) 13(-1.9,0.975) 14(-1.9,0.325) 15(-1.9,-0.325) 16(-1.9,-0.975)
  rect 2.108x2.108 smd: PAD(0,0)
QFN16_4X4_PAD2_5X2_5
  oval 0.356x0.991 smd: 1(-0.975,-1.974) 2(-0.325,-1.974) 3(0.325,-1.974) 4(0.975,-1.974) 9(0.975,1.974) 10(0.325,1.974) 11(-0.325,1.974) 12(-0.975,1.974)
  oval 0.991x0.356 smd: 5(1.974,-0.975) 6(1.974,-0.325) 7(1.974,0.325) 8(1.974,0.975) 13(-1.974,0.975) 14(-1.974,0.325) 15(-1.974,-0.325) 16(-1.974,-0.975)
  rect 2.489x2.489 smd: PAD(0,0)
QFN32_5X5_PAD3_1X3_1
  oval 0.305x0.889 smd: 1(-1.75,-2.45) 2(-1.25,-2.45) 3(-0.75,-2.45) 4(-0.25,-2.45) 5(0.25,-2.45) 6(0.75,-2.45) 7(1.25,-2.45) 8(1.75,-2.45) 17(1.75,2.45) 18(1.25,2.45) 19(0.75,2.45) 20(0.25,2.45) 21(-0.25,2.45) 22(-0.75,2.45) 23(-1.25,2.45) 24(-1.75,2.45)
  oval 0.889x0.305 smd: 9(2.45,-1.75) 10(2.45,-1.25) 11(2.45,-0.75) 12(2.45,-0.25) 13(2.45,0.25) 14(2.45,0.75) 15(2.45,1.25) 16(2.45,1.75) 25(-2.45,1.75) 26(-2.45,1.25) 27(-2.45,0.75) 28(-2.45,0.25) 29(-2.45,-0.25) 30(-2.45,-0.75) 31(-2.45,-1.25) 32(-2.45,-1.75)
  rect 3.099x3.099 smd: PAD(0,0)
QFN32_5X5_PAD3_3X3_3
  oval 0.305x0.889 smd: 1(-1.75,-2.45) 2(-1.25,-2.45) 3(-0.75,-2.45) 4(-0.25,-2.45) 5(0.25,-2.45) 6(0.75,-2.45) 7(1.25,-2.45) 8(1.75,-2.45) 17(1.75,2.45) 18(1.25,2.45) 19(0.75,2.45) 20(0.25,2.45) 21(-0.25,2.45) 22(-0.75,2.45) 23(-1.25,2.45) 24(-1.75,2.45)
  oval 0.889x0.305 smd: 9(2.45,-1.75) 10(2.45,-1.25) 11(2.45,-0.75) 12(2.45,-0.25) 13(2.45,0.25) 14(2.45,0.75) 15(2.45,1.25) 16(2.45,1.75) 25(-2.45,1.75) 26(-2.45,1.25) 27(-2.45,0.75) 28(-2.45,0.25) 29(-2.45,-0.25) 30(-2.45,-0.75) 31(-2.45,-1.25) 32(-2.45,-1.75)
  rect 3.302x3.302 smd: PAD(0,0)
R0201
  rect 0.305x0.406 smd: 1(-0.318,0) 2(0.318,0)
R0402
  rect 0.61x0.61 smd: 1(-0.495,0) 2(0.495,0)
R0603
  rect 1.092x1.194 smd: 1(-0.851,0) 2(0.851,0)
R0603#2
  rect 0.889x0.813 smd: 1(-0.737,0) 2(0.737,0)
R0805
  rect 1.295x1.397 smd: 1(-0.953,0) 2(0.953,0)
RM10
  rect 0.305x1.321 smd: 1(-1,-2.171) 2(-0.5,-2.171) 3(0,-2.171) 4(0.5,-2.171) 5(1,-2.171) 6(1,2.171) 7(0.5,2.171) 8(0,2.171) 9(-0.5,2.171) 10(-1,2.171)
SON10_2X2_PAD1_5X0_9
  oval 0.203x0.762 smd: 1(-0.8,-1) 2(-0.4,-1) 3(0,-1) 4(0.4,-1) 5(0.8,-1) 6(0.8,1) 7(0.4,1) 8(0,1) 9(-0.4,1) 10(-0.8,1)
  rect 1.499x0.889 smd: PAD(0,0)
SOT23
  rect 1.016x1.397 smd: 1(-0.94,-1.118) 2(0.94,-1.118) 3(0,1.118)
TBGA24
  round 0.33 smd: A2(-2,-1) A3(-2,0) A4(-2,1) A5(-2,2) B1(-1,-2) B2(-1,-1) B3(-1,0) B4(-1,1) B5(-1,2) C1(0,-2) C2(0,-1) C3(0,0) C4(0,1) C5(0,2) D1(1,-2) D2(1,-1) D3(1,0) D4(1,1) D5(1,2) E1(2,-2) E2(2,-1) E3(2,0) E4(2,1) E5(2,2)
TSML150W160H160
  rect 0.762x1.651 smd: 1(-1.27,1.587) 2(0,1.587) 3(1.27,1.587) 4(1.27,-1.587) 5(0,-1.587) 6(-1.27,-1.587)
unnamed#2
  round 1.016 smd: (0,0)
WLCSP6
  round 0.254 smd: A1(-0.5,-0.25) A2(-0.5,0.25) B1(0,-0.25) B2(0,0.25) C1(0.5,-0.25) C2(0.5,0.25)
YSML98W79H35
  rect 1.092x0.991 smd: 1(-0.921,-0.72) 2(0.921,-0.72) 3(0.921,0.72) 4(-0.921,0.72)
YSML126W98H47
  rect 1.397x1.194 smd: 1(-1.2,-0.95) 2(1.2,-0.95) 3(1.2,0.95) 4(-1.2,0.95)

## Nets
1.0V: C17.1(N1) C19.1(N1) C20.1(N1) C21.1(N1) E1.1(N1) L4.2(N2) R7.2(N2)
1.35V: C145.1(N1) C148.1(N1) E2.1(N1) L2.2(N2) R62.1(N1)
1V8: C1.1(N1) C10.1(N1) C22.1(N1) C25.1(N1) C46.1(N1) C48.1(N1) C49.1(N1) C50.1(N1) C51.1(N1) C52.1(N1) C53.1(N1) C65.1(N1) C67.1(N1) C69.1(N1) C76.1(N1) C77.1(N1) C78.1(N1) C82.1(N1) C83.1(N1) C90.1(N1) C103.1(N1) C104.1(N1) C105.1(N1) C106.1(N1) C107.1(N1) C108.1(N1) C109.1(N1) C110.1(N1) C111.1(N1) C112.1(N1) C113.1(N1) C114.1(N1) C115.1(N1) C116.1(N1) C117.1(N1) C118.1(N1) C119.1(N1) C120.1(N1) C121.1(N1) C122.1(N1) C140.1(N1) C152.1(N1) C153.1(N1) C154.1(N1) C158.1(N1) C159.1(N1) C160.1(N1) C161.1(N1) C162.1(N1) C163.2(N2) C166.2(N2) C168.1(N1) C174.1(N1) E3.2(N2) E4.1(N1) E5.1(N1) L12.1(N1) P1.10(N5) R8.1(N1) R13.1(N1) R14.1(N1) R44.1(N1) R45.1(N1) R46.2(N2) R47.2(N2) R74.1(N1) R76.1(N1) R78.1(N1) R79.1(N1) R83.1(N1) R84.2(N2) R122.2(N2) U1.1(VIN1) U1.2(VIN2) U1.3(VIN3) U1.4(EN) U1.15(VIN4) U1.16(VIN5) U4.A6(VCCO_MIO0_500_1) U4.B13(VCCO_MIO1_501_1) U4.C10(VCCO_MIO1_501_2) U4.D7(VCCO_MIO0_500_2) U4.E14(VCCO_MIO1_501_3) U4.F11(VCCO_34_6) U4.G4(RSVDVCC1) U4.H4(RSVDVCC3) U4.H9(VCCAUX_1) U4.H15(VCCO_34_7) U4.J4(RSVDVCC2) U4.J6(VCCPAUX_1) U4.J8(VCCAUX_2) U4.J12(VCCO_34_1) U4.K8(VCCO_0) U4.K9(VCCAUX_3) U4.L6(VCCPAUX_2) U4.M13(VCCO_34_2) U4.N10(VCCO_34_3) U4.P7(VCCO_34_4) U4.R14(VCCO_34_5) U7.1(VIN1) U7.2(VIN2) U7.3(VIN3) U7.4(EN) U7.15(VIN4) U7.16(VIN5) U11.1(VCCA) U13.B4(VCC) U15.8(REFSEL0) U15.11(REFSEL1) U15.14(REFSEL2) U15.28(VDD18_1) U15.30(VDD18_2) U15.32(VDDIO) Y1.4(VDD) Y2.4(VDD) Y3.4(VDD)
1V35: C54.1(N1) C55.1(N1) C56.1(N1) C57.1(N1) C58.1(N1) C59.1(N1) C60.1(N1) C61.1(N1) C86.1(N1) C87.1(N1) C88.1(N1) C89.1(N1) C91.1(N1) C92.1(N1) C94.1(N1) C95.1(N1) C96.1(N1) C97.1(N1) C100.1(N1) C151.1(N1) E2.2(N2) R41.2(N2) U2.A1(VDDQ_1) U2.A8(VDDQ_2) U2.B2(VDD_1) U2.C1(VDDQ_3) U2.C9(VDDQ_4) U2.D2(VDDQ_5) U2.D9(VDD_2) U2.E9(VDDQ_6) U2.F1(VDDQ_7) U2.G7(VDD_3) U2.H2(VDDQ_8) U2.H9(VDDQ_9) U2.K2(VDD_4) U2.K8(VDD_5) U2.N1(VDD_6) U2.N9(VDD_7) U2.R1(VDD_8) U2.R9(VDD_9) U4.B3(VCCO_DDR_502_1) U4.E4(VCCO_DDR_502_2) U4.F1(VCCO_DDR_502_3) U4.J2(VCCO_DDR_502_4) U4.M3(VCCO_DDR_502_5) U4.R4(VCCO_DDR_502_6) U14.1(VDDQSNS)
GND: C1.2(N2) C2.2(N2) C3.2(N2) C4.2(N2) C5.2(N2) C6.2(N2) C7.1(N1) C8.2(N2) C9.2(N2) C10.2(N2) C11.2(N2) C12.2(N2) C13.2(N2) C14.2(N2) C15.2(N2) C16.2(N2) C17.2(N2) C18.2(N2) C19.2(N2) C20.2(N2) C21.2(N2) C22.2(N2) C23.2(N2) C24.2(N2) C25.2(N2) C26.2(N2) C27.2(N2) C28.2(N2) C29.2(N2) C30.2(N2) C31.2(N2) C32.2(N2) C33.2(N2) C34.2(N2) C35.2(N2) C36.2(N2) C37.2(N2) C38.2(N2) C39.2(N2) C40.2(N2) C41.2(N2) C42.2(N2) C43.2(N2) C44.2(N2) C45.2(N2) C46.2(N2) C47.2(N2) C48.2(N2) C49.2(N2) C50.2(N2) C51.2(N2) C52.2(N2) C53.2(N2) C54.2(N2) C55.2(N2) C56.2(N2) C57.2(N2) C58.2(N2) C59.2(N2) C60.2(N2) C61.2(N2) C62.1(N1) C63.1(N1) C64.2(N2) C65.2(N2) C66.2(N2) C67.2(N2) C68.2(N2) C69.2(N2) C70.2(N2) C71.2(N2) C72.2(N2) C73.2(N2) C74.2(N2) C75.2(N2) C76.2(N2) C77.2(N2) C78.2(N2) C79.2(N2) C80.2(N2) C81.2(N2) C82.2(N2) C83.2(N2) C84.2(N2) C85.2(N2) C86.2(N2) C87.2(N2) C88.2(N2) C89.2(N2) C90.2(N2) C91.2(N2) C92.2(N2) C94.2(N2) C95.2(N2) C96.2(N2) C97.2(N2) C99.1(N1) C100.2(N2) C101.2(N2) C102.2(N2) C103.2(N2) C104.2(N2) C105.2(N2) C106.2(N2) C107.2(N2) C108.2(N2) C109.2(N2) C110.2(N2) C111.2(N2) C112.2(N2) C113.2(N2) C114.2(N2) C115.2(N2) C116.2(N2) C117.2(N2) C118.2(N2) C119.2(N2) C120.2(N2) C121.2(N2) C122.2(N2) C124.2(N2) C125.1(N1) C126.1(N1) C127.2(N2) C128.2(N2) C129.1(N1) C130.2(N2) C135.2(N2) C136.2(N2) C137.2(N2) C138.2(N2) C139.1(N1) C140.2(N2) C141.2(N2) C142.1(N1) C143.1(N1) C145.2(N2) C146.2(N2) C147.1(N1) C148.2(N2) C149.2(N2) C150.2(N2) C151.2(N2) C152.2(N2) C153.2(N2) C154.2(N2) C155.2(N2) C156.2(N2) C157.2(N2) C158.2(N2) C159.2(N2) C160.2(N2) C161.2(N2) C162.2(N2) C163.1(N1) C164.2(N2) C165.2(N2) C166.1(N1) C167.2(N2) C168.2(N2) C174.2(N2) C178.2(N2) D1.A(P) D2.A(P) E6.1(N1) P1.7(N4) P1.9(N5) P2.5(N5) P3.5(N5) Q1.2(S) Q2.2(S) Q4.2(S) R2.1(N1) R3.1(N1) R9.2(N2) R15.2(N2) R40.2(N2) R42.2(N2) R49.1(N1) R53.1(N1) R54.2(N2) R55.2(N2) R58.2(N2) R61.1(N1) R63.2(N2) R65.1(N1) R67.2(N2) R69.2(N2) R72.2(N2) R77.2(N2) R116.2(N2) R119.2(N2) R120.2(N2) R121.2(N2) R165.2(N2) RX1A.2(SH1) RX1A.3(SH2) RX1A.4(SH3) RX1A.5(SH4) T1.1(NC1) T1.2(PRI) T1.5(NC2) T5.1(NC1) T5.2(PRI) T5.5(NC2) TX1A.2(SH1) TX1A.3(SH2) TX1A.4(SH3) TX1A.5(SH4) U1.6(GND) U1.PAD U2.A9(VSS_1) U2.B1(VSSQ_1) U2.B3(VSS_2) U2.B9(VSSQ_2) U2.D1(VSSQ_3) U2.D8(VSSQ_4) U2.E1(VSS_3) U2.E2(VSSQ_5) U2.E8(VSSQ_6) U2.F9(VSSQ_7) U2.G1(VSSQ_8) U2.G8(VSS_4) U2.G9(VSSQ_9) U2.J2(VSS_5) U2.J8(VSS_6) U2.M1(VSS_7) U2.M9(VSS_8) U2.P1(VSS_9) U2.P9(VSS_10) U2.T1(VSS_11) U2.T9(VSS_12) U3.5(GND) U3.6(PGND_1) U3.7(PGND_2) U3.8(PGND_3) U3.PAD U4.A1(GND_1) U4.A11(GND_2) U4.B8(GND_3) U4.C5(GND_4) U4.C15(GND_5) U4.D2(GND_6) U4.D12(GND_7) U4.E5(GND_8) U4.E7(GND_9) U4.E8(RSVDGND) U4.E9(GND_10) U4.F10(GND_11) U4.G3(GND_12) U4.G5(GND_13) U4.G13(GND_14) U4.H6(GND_15) U4.H10(GND_16) U4.J5(GND_17) U4.J9(GND_18) U4.K4(GND_19) U4.K7(GND_20) U4.K10(GND_21) U4.K14(GND_22) U4.L1(GND_23) U4.L5(GND_24) U4.L11(GND_25) U4.M8(GND_26) U4.N5(GND_27) U4.N15(GND_28) U4.P2(GND_29) U4.P12(GND_30) U4.R9(GND_31) U5.A1(RX2A_N) U5.A2(RX2A_P) U5.A4(VSSA_1) U5.A5(TX_MON2) U5.A6(VSSA_2) U5.A12(VSSA_3) U5.B1(VSSA_4) U5.B2(VSSA_5) U5.B12(VSSA_6) U5.C1(RX2C_P) U5.C2(VSSA_7) U5.C4(TEST/ENABLE) U5.C7(VSSA_8) U5.C8(VSSA_9) U5.C9(VSSA_10) U5.C10(VSSA_11) U5.C11(VSSA_12) U5.C12(VSSA_13) U5.D1(RX2C_N) U5.D12(VSSD_1) U5.E1(RX2B_P) U5.F1(RX2B_N) U5.F3(VSSA_14) U5.F7(VSSD_2) U5.F9(VSSD_3) U5.F11(VSSD_4) U5.G1(VSSA_15) U5.G10(FB_CLK_N) U5.G12(VSSD_5) U5.H1(RX1B_P) U5.H2(VSSA_16) U5.H3(VSSA_17) U5.H5(VSSA_18) U5.H6(VSSA_19) U5.H7(VSSD_6) U5.H9(TX_FRAME_N) U5.H10(VSSD_7) U5.J1(RX1B_N) U5.J2(VSSA_20) U5.K1(RX1C_P) U5.K2(VSSA_21) U5.K12(VSSD_8) U5.L1(RX1C_N) U5.L2(VSSA_22) U5.L3(VSSA_23) U5.L7(VSSA_24) U5.L8(VSSA_25) U5.L9(VSSA_26) U5.L10(VSSA_27) U5.L11(VSSA_28) U5.L12(VSSA_29) U5.M4(VSSA_30) U5.M5(TX_MON1) U5.M6(VSSA_31) U6.1(GND) U6.19(PGND4) U6.20(PGND3) U6.21(PGND2) U6.22(PGND1) U6.PAD U7.6(GND) U7.PAD U8.C1(GND) U9.C1(GND) U10.4(GND) U11.4(GND) U13.B3(VSS) U14.4(PGND) U14.8(GND) U14.PAD U15.PAD(GND_FLAG) Y1.2(GND) Y2.2(GND) Y3.2(GND)
VCCPINT: C64.1(N1) C66.1(N1) C68.1(N1) C70.1(N1) C71.1(N1) C72.1(N1) C73.1(N1) C74.1(N1) C75.1(N1) E1.2(N2) U4.E10(VCCINT_1) U4.F9(VCCINT_2) U4.G6(VCCPINT_1) U4.G10(VCCINT_3) U4.H5(VCCPINT_2) U4.J10(VCCINT_4) U4.K5(VCCPINT_3) U4.L10(VCCINT_5)
VCCPLL: C85.1(N1) C178.1(N1) L12.2(N2) U4.F5(VCCPLL)
VDD33_USB: C165.1(N1) U15.20(VDD33) U15.23(ID)
VDD_INTERFACE: C32.1(N1) C33.1(N1) C38.1(N1) C43.1(N1) C44.1(N1) C45.1(N1) E4.2(N2) R5.1(N1) U5.H12(VDD_INTERFACE)
VDDA1P1_RX_VCO: C125.2(N2) R51.2(N2) U5.G2(RX_VCO_LDO_OUT) U5.G3(VDDA1P1_RX_VCO)
VIN: C8.1(N1) C9.1(N1) C62.2(N2) C135.1(N1) C136.1(N1) C137.1(N1) C138.1(N1) C157.1(N1) C164.1(N1) C167.1(N1) DS1.A(P) DS2.A(P) E7.2(N2) L1.1(N1) R56.1(N1) R59.2(N2) R75.1(N1) R80.1(N1) R81.1(N1) R221.1(N1) R222.1(N1) U6.14(VIN4) U6.15(VIN5) U6.16(VIN6) U6.25(VIN3) U6.26(VIN2) U6.27(VIN1) U11.8(VCCB) U14.10(VDD) U15.21(VBAT)
VIN_5V_USB: R71.1(N1) R73.1(N1) U8.A1(OUT1) U8.B1(OUT2) U9.A1(OUT1) U9.B1(OUT2) U10.1(VCC)
VIN_5V_USB_DATA: P2.1(N1) R70.1(N1) U9.A2(IN1) U9.B2(IN2)
VIN_5V_USB_POWER: P3.1(N1) R66.1(N1) R68.1(N1) U8.A2(IN1) U8.B2(IN2)
1P3_SUPPLY_A: C14.1(N1) C15.1(N1) C16.1(N1) C18.1(N1) C23.1(N1) C24.1(N1) C28.1(N1) C29.1(N1) C34.1(N1) C35.1(N1) C39.1(N1) C40.1(N1) U5.B9(VDDA1P3_TX_LO) U5.B10(VDDA1P3_TX_VCO_LDO) U5.E2(VDDA1P3_RX_LO) U5.F2(VDDA1P3_RX_VC_LDO) U5.J3(VDDA1P3_RX_SYNTH) U5.K3(VDDA1P3_TX_SYNTH) U7.9(SENSE) U7.10(VOUT1) U7.11(VOUT2) U7.12(VOUT3) U7.13(VOUT4) U7.14(VOUT5)
1P3_SUPPLY_B: C3.1(N1) C4.1(N1) C5.1(N1) C6.1(N1) C26.1(N1) C27.1(N1) C30.1(N1) C31.1(N1) C36.1(N1) C37.1(N1) C41.1(N1) C42.1(N1) C129.2(N2) C130.1(N1) L8.1(N1) L9.1(N1) U1.9(SENSE) U1.10(VOUT1) U1.11(VOUT2) U1.12(VOUT3) U1.13(VOUT4) U1.14(VOUT5) U5.A7(TX2A_N) U5.A8(TX2A_P) U5.A9(TX2B_N) U5.A10(TX2B_P) U5.B8(VDD_GPO) U5.D2(VDDA1P3_RX_RF) U5.D3(VDDA1P3_RX_TX) U5.E3(VDDA1P3_TX_LO_BUFFER) U5.F12(VDDS1P3_DIG) U5.K4(VDDAP3_BB) U5.M9(TX1B_P) U5.M10(TX1B_N)
ADM1177_SCL: R81.2(N2) U10.6(SCL) U11.7(SCLB)
ADM1177_SDA: R80.2(N2) U10.7(SDA) U11.6(SDAB)
ADP2114_VIN: C141.1(N1) R56.2(N2) U6.4(SCFG) U6.8(VDD) U6.10(V2SET) U6.31(V1SET)
COMP_1P8V: C142.2(N2) R60.1(N1) U6.2(COMP1)
COMP_1P35V: C143.2(N2) C144.1(N1) U6.7(COMP2)
CTRL_IN0: U4.F13(IO_L3P_T0_DQS_AD1P_35) U5.C5(CTRL_IN0)
CTRL_IN1: U4.F14(IO_L3N_T0_DQS_AD1N_35) U5.C6(CTRL_IN1)
CTRL_IN2: U4.G15(IO_L5P_T0_AD9P_35) U5.D6(CTRL_IN2)
CTRL_IN3: U4.F15(IO_L5N_T0_AD9N_35) U5.D5(CTRL_IN3)
DDR3_A0: R16.1(N1) U2.N3(A0) U4.P1(PS_DDR_A0_502)
DDR3_A1: R22.1(N1) U2.P7(A1) U4.N1(PS_DDR_A1_502)
DDR3_A2: R17.1(N1) U2.P3(A2) U4.M1(PS_DDR_A2_502)
DDR3_A3: R23.1(N1) U2.N2(A3) U4.M4(PS_DDR_A3_502)
DDR3_A4: R18.1(N1) U2.P8(A4) U4.P3(PS_DDR_A4_502)
DDR3_A5: R24.1(N1) U2.P2(A5) U4.P4(PS_DDR_A5_502)
DDR3_A6: R19.1(N1) U2.R8(A6) U4.P5(PS_DDR_A6_502)
DDR3_A7: R25.1(N1) U2.R2(A7) U4.M5(PS_DDR_A7_502)
DDR3_A8: R20.1(N1) U2.T8(A8) U4.P6(PS_DDR_A8_502)
DDR3_A9: R26.1(N1) U2.R3(A9) U4.N4(PS_DDR_A9_502)
